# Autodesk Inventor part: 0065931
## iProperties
Created: 2005-06
Part Number: 0065931
Material: Stahl
Document SubType Name: Modeling
Designer: Armin Walder
Cost Center: 0.03 kg
Authority: 3830.9 mm^3
SaveDate: 2006-09-27
SaveTime: 12:51
FileName: 0065931
TotalMass: 0.03 kg
TotalVolume: 3830.9 mm^3
Author: Armin Walder
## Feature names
1. Drehung1 [Revolution]
2. Fase1 [Chamfer]
3. Fase2 [Chamfer]
4. Bohrung1 [Hole]
5. Extrusion1
6. Runde Anordnung1 [Circular Pattern]
7. Bohrung3 [Hole]
8. Fase3 [Chamfer]
9. Bohrung4 [Hole]
